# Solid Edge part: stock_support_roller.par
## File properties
Title: Stock support roller
Author: vicky raina
Template: Normal.par
Last saved by: Robert a Rhodes jr
Revision: 9
Application: Solid Edge
Material: aluminum
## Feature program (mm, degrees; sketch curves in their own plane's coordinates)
sketch for "unnamed RevolvedProtrusion 1" plane through (0, 0, 0) normal (0, -1, 0) x-axis (1, 0, 0)
  line (60, 0) -> (60, 18.669)
  line (60, 18.669) -> (15.55, 18.669)
  line (15.55, 18.669) -> (15.55, 92.075)
  line (15.55, 92.075) -> (-2.2388, 92.075)
  line (-2.2388, 92.075) -> (-111.45, 29.0219)
  line (-220.6612, 92.075) -> (-111.45, 29.0219)
  line (-238.45, 92.075) -> (-220.6612, 92.075)
  line (-238.45, 18.669) -> (-238.45, 92.075)
  line (-282.9, 18.669) -> (-238.45, 18.669)
  line (-282.9, 0) -> (-282.9, 18.669)
revolve "unnamed RevolvedProtrusion 1" add full turn 360 deg about sketch line (-282.9, 0) -> (60, 0)
chamfer "unnamed Chamfer 1"
fillet "unnamed Round 1"
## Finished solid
Body 1: solid body, 14 faces, 13 edges, 0 vertices.
  Faces by surface: cone 4, cylinder 4, plane 4, torus 2
  Edges by curve: circle 13
Bounding box of the edges (mm; curved faces can reach further): 342.900 x 184.150 x 184.150, from (-282.9, -92.075, -92.075) to (60, 92.075, 92.075).
Cylindrical faces by radius (mm): R18.669 x2, R92.075 x2
Conical faces (half-angle, radius in mm at the cone's reference point): 30 deg R29.0219 x1, 30 deg R92.075 x1, 45 deg R17.0942 x1, 45 deg R18.669 x1
Toroidal faces (ring radius, tube radius in mm): R20.2438 r1.5748 x2
Planar faces by outward normal: +x 2, -x 2
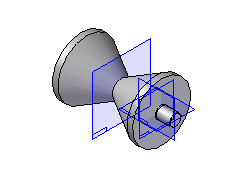
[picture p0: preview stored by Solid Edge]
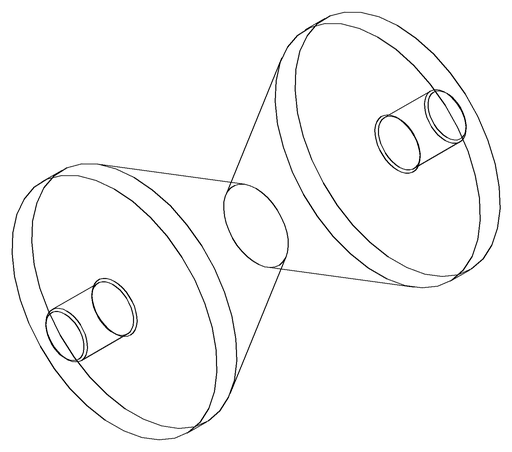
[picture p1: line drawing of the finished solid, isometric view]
